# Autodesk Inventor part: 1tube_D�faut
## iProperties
Created: 2011-01
Part Number: 1tube_D�faut
Document SubType Name: Modeling
Designer: eric
Density: 1 g/cm^3
Mass: 45.6973 g
Surface Area: 918.168 cm^2
Volume: 45.6973 cm^3
Author: eric
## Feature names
1. Base1
